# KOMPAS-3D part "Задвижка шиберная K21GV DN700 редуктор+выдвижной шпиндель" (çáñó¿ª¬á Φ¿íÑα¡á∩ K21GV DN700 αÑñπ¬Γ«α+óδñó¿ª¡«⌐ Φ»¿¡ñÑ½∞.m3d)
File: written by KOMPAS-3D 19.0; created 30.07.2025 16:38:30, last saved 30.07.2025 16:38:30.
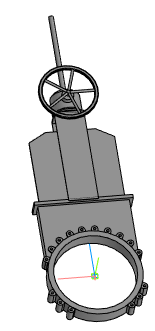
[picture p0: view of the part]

Document properties: Полное имя файла: Задвижка шиберная K21GV DN700 редуктор+выдвижной шпиндель.a3d

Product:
- Part/product: Задвижка шиберная K21GV DN700 редуктор+выдвижной шпиндель
    Масса: 540.76

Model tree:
1. Операция без истории:1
